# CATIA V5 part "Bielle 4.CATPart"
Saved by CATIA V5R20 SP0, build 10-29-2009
Part number: Bielle 4
Publications: "Arête", "Arête1", "Arête2", "Face"
Bounding box of the stored display mesh (mm): x -10 to 10, y 121.836 to 197.836, z 156.873 to 176.86
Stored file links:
  C:\Users\thinkmotion1\Desktop\Khaled_IAO_Pack2\IAO_2010_1412_jclement\Non_Optimise\Bielle 4.CATPart
  C:\Users\thinkmotion1\Desktop\Khaled_IAO_Pack2\IAO_2010_1412_jclement\Non_Optimise\Synthese IAO_2.CATProduct
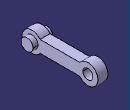
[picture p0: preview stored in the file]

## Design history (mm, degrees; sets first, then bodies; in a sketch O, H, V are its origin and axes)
Set1
  DatumCurve1: linked copy from another document
  DatumCurve2: linked copy from another document
Body1 (main body)
  Sketch1 on yz-plane, origin (0, 0, 0), H (0, 1, 0), V (0, 0, 1)
    arc A1 centre (131.8357, 166.8666) radius 10 from (139.8357, 172.8666) to (139.8357, 160.8666) ccw
    point P1 (131.8357, 166.8666)
    reference projected arc E1 centre (131.8357, 166.8666) radius 10 from (135.7377, 157.6593) to (139.5822, 173.1906) ccw from edge of DatumCurve1
    arc A2 centre (187.8357, 166.8666) radius 10 from (179.8357, 160.8666) to (179.8357, 172.8666) ccw
    point P2 (187.8357, 166.8666)
    line L1 (139.8357, 172.8666) -> (179.8357, 172.8666)
    line L2 (179.8357, 160.8666) -> (139.8357, 160.8666)
    radius A2 = 10
    distance P2 P1 V = 0
    distance P2 P1 = 56
    distance L1 L2 = 12
    coincidence: A1 E1
    horizontal: L1 H, L2 H
    equidistance: L1 L2 P2
  Pad1: profile Sketch1, direction (1, 0, 0), length 5, mirrored extent
  Sketch2 on end face of Pad1, origin (5, 0, 0), H (0, 1, 0), V (0, 0, 1)
    circle A1 centre (131.8357, 166.8666) radius 6
    reference projected circle E1 centre (131.8357, 166.8666) radius 6 from edge of DatumCurve2
    coincidence: A1 E1
  Pad2: profile Sketch2, direction (1, 0, 0), length 5, opposite side length 15
  Sketch3 on end face of Pad1, origin (5, 0, 0), H (0, 1, 0), V (0, 0, 1)
    circle A1 centre (187.8357, 166.8666) radius 5
    reference projected arc E1 centre (187.8357, 166.8666) radius 10 from (179.8357, 160.8666) to (179.8357, 172.8666) ccw from edge [face of Pad1 from Sketch1.A2 | end face of Pad1]
    radius A1 = 5
    concentricity: A1 E1
  Pocket1: profile Sketch3, direction (-1, 0, 0), through (limit type 6)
